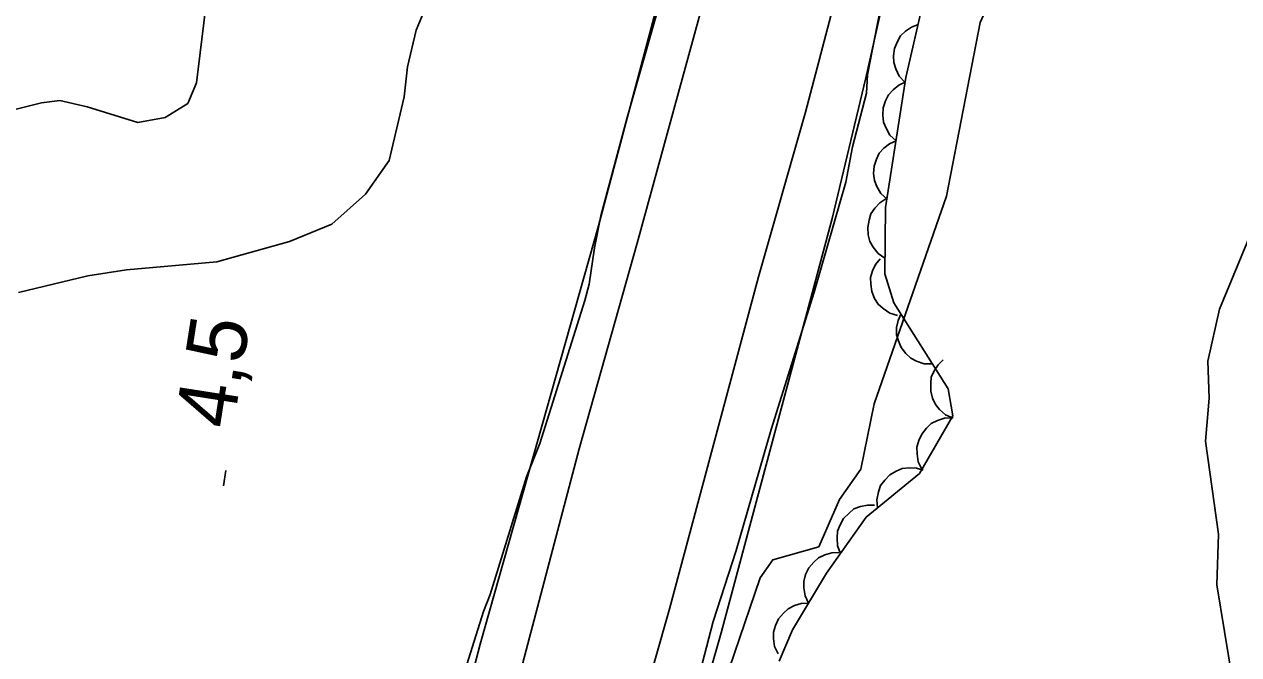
# Model space of a CAD drawing. Extents: x 282461 to 284471, y 5554090 to 5557646.
# Drawn here: x 283325.8 to 283387.5, y 5555349.2 to 5555381.2 of the extents above; entities that cross this region are included whole.
import ezdxf

# ---------------------------------------------------------------- set-up
doc = ezdxf.new("R2010")
doc.units = 0
for name, color, linetype in [('Niveau 1', 7, 'Continuous'), ('Niveau 2', 7, 'Continuous'), ('Niveau 21', 7, 'Continuous'), ('Niveau 3', 7, 'Continuous'), ('Niveau 44', 7, 'Continuous')]:
    doc.layers.add(name, color=color, linetype=linetype)

msp = doc.modelspace()

# ---------------------------------------------------------------- linework, layer by layer
at = {"layer": 'Niveau 1'}
for points in [[(283369.19, 5555427.32), (283368.58, 5555424.88), (283367.79, 5555422.44), (283366.63, 5555417.44), (283365.99, 5555413.08), (283365.55, 5555411.22), (283364.32, 5555406.92), (283363.22, 5555401.86), (283360.61, 5555391.8), (283360.34, 5555390.11), (283359.79, 5555387.73), (283357.89, 5555381.62), (283356.44, 5555376.5), (283355.1, 5555371.5), (283354.77, 5555369.88), (283354.51, 5555368.02), (283354.28, 5555367.2), (283351.99, 5555359.93), (283351.31, 5555358.24), (283349.47, 5555352.25), (283349.13, 5555351.38), (283346.67, 5555343.58)], [(283359.25, 5555344.88), (283360.8, 5555350.87), (283361.98, 5555354.48), (283363.76, 5555360.64), (283365.94, 5555367.62), (283367.56, 5555373.21), (283367.89, 5555375.01), (283368.61, 5555377.74), (283368.66, 5555378.67), (283369.81, 5555384.6), (283369.79, 5555385.87), (283372.52, 5555395.47), (283372.79, 5555397.27), (283373.24, 5555399.01), (283373.34, 5555399.94), (283374.9, 5555405.24), (283376.57, 5555411.46), (283376.62, 5555412.1), (283376.9, 5555413.55), (283377.21, 5555416.34), (283377.66, 5555418.08), (283380.45, 5555427.1)]]:
    msp.add_lwpolyline(points, dxfattribs=at)
at = {"layer": 'Niveau 2'}
for points in [[(283386.38, 5555427.71), (283385.24, 5555421.41), (283383.38, 5555416.01), (283381.53, 5555411.86), (283379.42, 5555403.8), (283378.24, 5555401.58), (283376.57, 5555396.38), (283376.12, 5555393.54), (283375.84, 5555386.24), (283375.19, 5555383.09), (283374.39, 5555381.33), (283372.68, 5555372.5), (283368.99, 5555361.94), (283368.32, 5555358.62), (283367.23, 5555357.08), (283366.18, 5555354.67), (283363.84, 5555354.01), (283363.19, 5555353.1), (283360.59, 5555345.44)], [(283324.68, 5555376.76), (283326.65, 5555377.24), (283327.58, 5555377.37), (283328.98, 5555377.04), (283331.55, 5555376.25), (283332.94, 5555376.5), (283334.09, 5555377.21), (283334.54, 5555378.26), (283334.99, 5555382.01)], [(283346.21, 5555382.16), (283345.7, 5555380.94), (283345.26, 5555379.08), (283345.1, 5555377.56), (283344.33, 5555374.31), (283343.13, 5555372.61), (283341.41, 5555371.08), (283339.27, 5555370.19), (283335.56, 5555369.16), (283330.98, 5555368.76), (283329.01, 5555368.45), (283325.48, 5555367.6)], [(283388.15, 5555370.61), (283386.56, 5555366.75), (283385.96, 5555364.11), (283386.03, 5555362.23), (283385.84, 5555360.04), (283386.51, 5555355.31), (283386.43, 5555352.74), (283387.21, 5555348), (283388.34, 5555344.06)]]:
    msp.add_lwpolyline(points, dxfattribs=at)
at = {"layer": 'Niveau 21'}
for points in [[(283343.15, 5555297.48), (283344.82, 5555302.89), (283346.64, 5555309.77), (283350.04, 5555321.98), (283352.61, 5555330.06), (283355.72, 5555341.46), (283358.57, 5555351.46), (283363.11, 5555368.4), (283365.5, 5555376.77), (283369.96, 5555393.73), (283371.4, 5555399.48), (283375.63, 5555415.07), (283377.3, 5555421.58), (283383.42, 5555443.74), (283388.94, 5555463.12), (283392.46, 5555474.87), (283402.79, 5555506.48), (283405.51, 5555513.87), (283407.52, 5555520.57), (283413.11, 5555536.65), (283414.13, 5555540), (283418.84, 5555553.93)], [(283336.52, 5555296.58), (283345.36, 5555329.07), (283349.01, 5555340.73), (283353.99, 5555359.65), (283356.95, 5555370.11), (283360.62, 5555383.54), (283367.57, 5555410.27), (283370.08, 5555419.06), (283377.96, 5555448.27), (283379.69, 5555453.91), (283380.81, 5555457.98), (283384.16, 5555469.1), (283390.82, 5555490.22), (283395.1, 5555502.68), (283399.67, 5555516.53), (283403.67, 5555529), (283406.23, 5555536.33), (283411.71, 5555552.99)], [(283344.73, 5555292.08), (283347.9, 5555303.94), (283352.03, 5555317.89), (283355.38, 5555328.71), (283357.43, 5555336.24), (283359.48, 5555344.26), (283361.21, 5555350.31), (283366.86, 5555371.37), (283368.58, 5555378.52), (283370.45, 5555386.89), (283376.58, 5555411.34), (283378.92, 5555420.12), (283381.32, 5555428.44), (283387.66, 5555451.48), (283392.52, 5555468.36), (283394.86, 5555476.04), (283398.35, 5555485.88), (283400.13, 5555492.11), (283406.04, 5555510.39), (283408.05, 5555516.97), (283412.1, 5555528.8), (283414.21, 5555534.11), (283415.8, 5555538.57), (283420.56, 5555553.08)], [(283405.35, 5555543.77), (283400.81, 5555527.66), (283393.61, 5555506.3), (283389.72, 5555495.23), (283386, 5555483.77), (283382.31, 5555471.72), (283379.8, 5555462.88), (283377.9, 5555456.71), (283376, 5555449.96), (283373.72, 5555441.52), (283371.34, 5555432.28), (283369.72, 5555426.52), (283367.84, 5555418.55), (283360.38, 5555391.33), (283354.98, 5555371), (283348.96, 5555349.72), (283345.74, 5555337.39), (283343.68, 5555330.47), (283339.28, 5555314.89), (283337.62, 5555308.27), (283335.49, 5555301.46), (283330.1, 5555282.05)]]:
    msp.add_lwpolyline(points, dxfattribs=at)
at = {"layer": 'Niveau 3'}
msp.add_line((283335.91, 5555357.77), (283336.03, 5555358.56), dxfattribs=at)
at = {"layer": 'Niveau 44'}
for points in [[(283364.17, 5555348.86), (283364.84, 5555350.45), (283366.57, 5555353.34), (283368.59, 5555356.18), (283371.3, 5555358.41), (283372.99, 5555361.34), (283372.76, 5555362.71), (283369.99, 5555367.08), (283369.53, 5555368.56), (283369.58, 5555371.93), (283370.61, 5555378.53), (283371.51, 5555382.44)], [(283370.56, 5555378.3), (283370.27, 5555378.61), (283370.09, 5555378.97), (283369.99, 5555379.29), (283369.98, 5555379.64), (283370.03, 5555380.01), (283370.18, 5555380.36), (283370.33, 5555380.65), (283370.59, 5555380.89), (283370.9, 5555381.1), (283371.23, 5555381.23)], [(283370.11, 5555375.32), (283369.8, 5555375.61), (283369.6, 5555375.96), (283369.47, 5555376.27), (283369.43, 5555376.62), (283369.46, 5555376.99), (283369.58, 5555377.35), (283369.72, 5555377.65), (283369.96, 5555377.91), (283370.25, 5555378.14), (283370.57, 5555378.3)], [(283369.65, 5555372.35), (283369.34, 5555372.64), (283369.13, 5555372.99), (283369.01, 5555373.3), (283368.97, 5555373.65), (283369, 5555374.02), (283369.12, 5555374.38), (283369.25, 5555374.68), (283369.49, 5555374.94), (283369.78, 5555375.17), (283370.11, 5555375.32)], [(283369.54, 5555369.35), (283369.2, 5555369.59), (283368.95, 5555369.91), (283368.78, 5555370.19), (283368.69, 5555370.54), (283368.67, 5555370.91), (283368.74, 5555371.28), (283368.83, 5555371.6), (283369.03, 5555371.89), (283369.28, 5555372.16), (283369.59, 5555372.36)], [(283370.19, 5555366.44), (283369.79, 5555366.56), (283369.45, 5555366.79), (283369.2, 5555367.01), (283369.01, 5555367.3), (283368.87, 5555367.65), (283368.82, 5555368.03), (283368.81, 5555368.36), (283368.91, 5555368.7), (283369.07, 5555369.03), (283369.3, 5555369.31)], [(283371.96, 5555363.97), (283371.54, 5555363.98), (283371.15, 5555364.12), (283370.86, 5555364.26), (283370.6, 5555364.5), (283370.37, 5555364.8), (283370.23, 5555365.15), (283370.13, 5555365.46), (283370.14, 5555365.82), (283370.21, 5555366.18), (283370.35, 5555366.51)], [(283373.01, 5555361.22), (283372.63, 5555361.39), (283372.32, 5555361.66), (283372.11, 5555361.91), (283371.96, 5555362.23), (283371.87, 5555362.59), (283371.87, 5555362.98), (283371.9, 5555363.3), (283372.05, 5555363.62), (283372.25, 5555363.93), (283372.51, 5555364.18)], [(283371.42, 5555358.63), (283371.24, 5555359), (283371.18, 5555359.4), (283371.17, 5555359.74), (283371.26, 5555360.08), (283371.42, 5555360.41), (283371.66, 5555360.71), (283371.9, 5555360.94), (283372.21, 5555361.1), (283372.57, 5555361.21), (283372.93, 5555361.23)], [(283369.17, 5555356.66), (283369.13, 5555357.07), (283369.21, 5555357.47), (283369.32, 5555357.79), (283369.53, 5555358.07), (283369.79, 5555358.33), (283370.12, 5555358.52), (283370.42, 5555358.65), (283370.77, 5555358.69), (283371.15, 5555358.67), (283371.49, 5555358.57)], [(283367.28, 5555354.34), (283367.13, 5555354.73), (283367.11, 5555355.14), (283367.13, 5555355.47), (283367.26, 5555355.8), (283367.44, 5555356.12), (283367.72, 5555356.39), (283367.97, 5555356.6), (283368.3, 5555356.72), (283368.66, 5555356.8), (283369.02, 5555356.79)], [(283365.65, 5555351.81), (283365.48, 5555352.19), (283365.42, 5555352.59), (283365.42, 5555352.92), (283365.51, 5555353.26), (283365.68, 5555353.6), (283365.93, 5555353.89), (283366.16, 5555354.11), (283366.48, 5555354.27), (283366.84, 5555354.37), (283367.2, 5555354.39)], [(283364.11, 5555349.23), (283363.93, 5555349.61), (283363.87, 5555350.01), (283363.87, 5555350.34), (283363.97, 5555350.68), (283364.13, 5555351.02), (283364.38, 5555351.31), (283364.62, 5555351.53), (283364.94, 5555351.69), (283365.29, 5555351.79), (283365.65, 5555351.81)]]:
    msp.add_lwpolyline(points, dxfattribs=at)

# ---------------------------------------------------------------- texts
at = {"layer": 'Niveau 3'}
msp.add_text('4,5  ', height=3, rotation=81.09575, dxfattribs=at).set_placement((283336.39, 5555360.61))

doc.saveas('drawing.dxf')
